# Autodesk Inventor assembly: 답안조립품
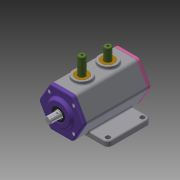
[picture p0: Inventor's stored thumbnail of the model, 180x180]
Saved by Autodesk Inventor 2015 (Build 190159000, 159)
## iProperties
Created: 2021-06
Part Number: 답안조립품
Document SubType Name: Assembly
Designer: now
Author: now
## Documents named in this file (11)
- C:\Users\now\Desktop\710606V1028\답안조립품.iam
- C:\Users\now\Desktop\710606V1028\뒷커버.ipt
- C:\Users\now\Desktop\710606V1028\베어링 6203.ipt
- C:\Users\now\Desktop\710606V1028\베어링 6302.ipt
- C:\Users\now\Desktop\710606V1028\본체.ipt
- C:\Users\now\Desktop\710606V1028\볼트 M4.ipt
- C:\Users\now\Desktop\710606V1028\부시.ipt
- C:\Users\now\Desktop\710606V1028\슬라이더.ipt
- C:\Users\now\Desktop\710606V1028\앞커버.ipt
- C:\Users\now\Desktop\710606V1028\오일실.ipt
- C:\Users\now\Desktop\710606V1028\편심축.ipt
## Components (10 placed, 3 different names)
1. 7-베어링 6203:1
2. 8-오일실:1
3. 9-M4-소켓머리:1
4. 9-M4-소켓머리:3
5. 9-M4-소켓머리:4
6. 9-M4-소켓머리:5
7. 9-M4-소켓머리:2
8. 9-M4-소켓머리:6
9. 9-M4-소켓머리:7
10. 9-M4-소켓머리:8
